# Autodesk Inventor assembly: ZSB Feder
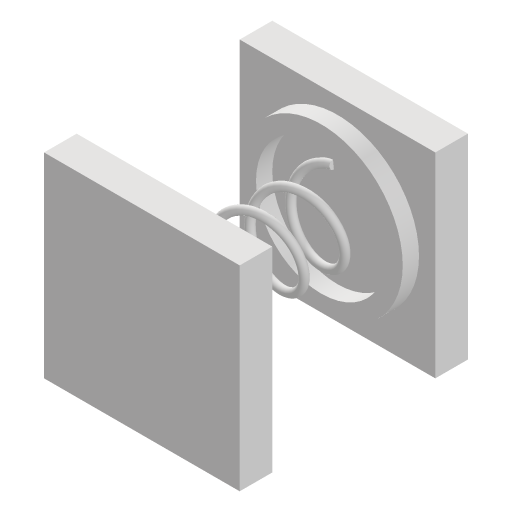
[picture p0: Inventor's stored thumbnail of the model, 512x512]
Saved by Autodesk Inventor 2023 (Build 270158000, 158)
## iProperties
Created: 2023-02
Part Number: ZSB Feder
Document SubType Name: Assembly
Designer: Nicole Höfler
Author: Nicole Höfler
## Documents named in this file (3)
- C:\Users\info\OneDrive\Desktop\Neuer Ordner\Feder\ZSB Feder.iam
- C:\Users\info\OneDrive\Desktop\Neuer Ordner\Feder\Federteller.ipt
- C:\Users\info\OneDrive\Desktop\Neuer Ordner\Feder\Feder.ipt
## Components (3 placed, 2 different names)
1. Federteller:1 — Fluchtend:1, Fluchtend:2, Weg Platten, Passend:2, Passend:3
2. Federteller:2 — Fluchtend:1, Fluchtend:2, Weg Platten, Passend:4
3. Feder:1 — Passend:2, Passend:3, Passend:4
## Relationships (6: Mate 4, Flush 2)
- Fluchtend:1 [Flush]: Federteller:1 ↔ Federteller:2
- Fluchtend:2 [Flush]: Federteller:1 ↔ Federteller:2
- Weg Platten [Mate]: Federteller:1 ↔ Federteller:2
- Passend:2 [Mate]: Federteller:1 ↔ Feder:1
- Passend:3 [Mate]: Federteller:1 ↔ Feder:1
- Passend:4 [Mate]: Federteller:2 ↔ Feder:1
